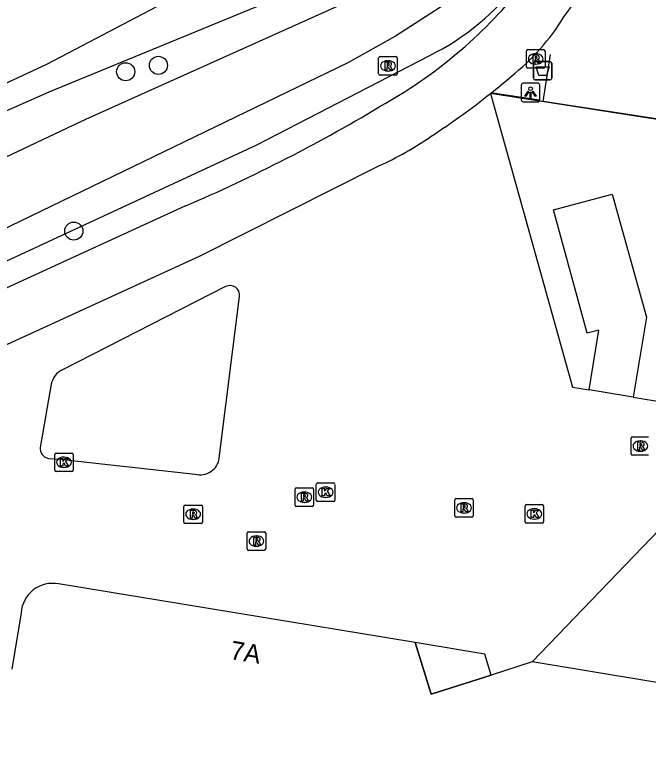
# Model space of a CAD drawing. Extents: x 161094 to 161705, y 379509 to 380907.
# Drawn here: x 161323.43 to 161357.68, y 379952.77 to 379992.35 of the extents above; entities that cross this region are included whole.
import ezdxf

# ---------------------------------------------------------------- set-up
doc = ezdxf.new("R2010")
doc.units = 0
for name, color, linetype in [('IMGEO_Afvalbak', 7, 'Continuous'), ('IMGEO_Boom', 7, 'Continuous'), ('IMGEO_Gemengd_bos', 7, 'Continuous'), ('IMGEO_Groenvoorziening', 7, 'Continuous'), ('IMGEO_Hek', 7, 'Continuous'), ('IMGEO_Kolk', 7, 'Continuous'), ('IMGEO_Lichtpunt', 7, 'Continuous'), ('IMGEO_Pand', 7, 'Continuous'), ('IMGEO_Pand_nummerreeks', 7, 'Continuous'), ('IMGEO_Pand_overbouw', 7, 'Continuous'), ('IMGEO_Rijbaan_lokaal_gesloten', 7, 'Continuous'), ('IMGEO_Rioolput', 7, 'Continuous'), ('IMGEO_Voetpad_open', 7, 'Continuous'), ('IMGEO_Waterloop', 7, 'Continuous')]:
    doc.layers.add(name, color=color, linetype=linetype)

msp = doc.modelspace()

# ---------------------------------------------------------------- linework, layer by layer
at = {"layer": 'IMGEO_Afvalbak'}
for p, q in [((161351.474, 379988.924), (161351.474, 379989.724)), ((161351.474, 379989.724), (161351.474, 379988.924)), ((161351.574, 379989.824), (161352.364, 379989.824)), ((161352.364, 379989.824), (161351.574, 379989.824)), ((161352.464, 379989.724), (161352.464, 379988.924)), ((161352.464, 379988.924), (161352.464, 379989.724)), ((161352.364, 379988.824), (161351.574, 379988.824)), ((161351.574, 379988.824), (161352.364, 379988.824))]:
    msp.add_line(p, q, dxfattribs=at)
msp.add_lwpolyline([(161351.617, 379989.538), (161352.321, 379989.538), (161352.172, 379989.068), (161351.766, 379989.068), (161351.617, 379989.538)], dxfattribs=at)
for centre, start, end in [((161351.574, 379989.724), 90, 180), ((161351.574, 379989.724), 90, 180), ((161352.364, 379989.724), 0, 90), ((161352.364, 379989.724), 360, 90), ((161351.574, 379988.924), 180, 270), ((161351.574, 379988.924), 180, 270), ((161352.364, 379988.924), 270, 0), ((161352.364, 379988.924), 270, 0)]:
    msp.add_arc(centre, 0.1, start, end, dxfattribs=at)
at = {"layer": 'IMGEO_Boom'}
for centre in [(161331.207, 379989.613), (161329.435, 379989.266), (161326.632, 379980.661)]:
    msp.add_circle(centre, 0.489, dxfattribs=at)
at = {"layer": 'IMGEO_Gemengd_bos'}
for points in [[(161333.512, 380038.343), (161333.176, 380032.678), (161343.848, 380009.856), (161345.909, 380004.475), (161345.846, 380002.276), (161345.022, 380001.282), (161342.303, 379999.185), (161336.014, 379995.373), (161325.162, 379989.659), (161249.827, 379954.657)], [(161336.371, 380036.456), (161336.02, 380036.34), (161334.235, 380035.507), (161334.347, 380033.968), (161334.211, 380033.487), (161335.124, 380031.714), (161344.815, 380009.148), (161345.747, 380007.474), (161346.951, 380004.344), (161347.178, 380000.806), (161346.961, 380000), (161346.828, 379999.503), (161346.335, 379998.76), (161344.226, 379996.702), (161341.864, 379995.267), (161336.806, 379992.91), (161325.289, 379988.164), (161318.516, 379985.174), (161250.264, 379953.685)]]:
    msp.add_lwpolyline(points, dxfattribs=at)
at = {"layer": 'IMGEO_Groenvoorziening'}
msp.add_lwpolyline([(161253.412, 379946.694), (161303.367, 379969.522), (161310.516, 379973.076), (161316.928, 379975.983), (161319.974, 379977.646), (161336.524, 379985.328), (161345.842, 379990.137)], dxfattribs=at)
msp.add_arc((161340.204, 380001.802), 12.956, 295.7967, 352.005, dxfattribs=at)
at = {"layer": 'IMGEO_Hek'}
for points in [[(161360.805, 379986.31), (161351.994, 379987.669), (161352.393, 379990.207)], [(161351.787, 379987.734), (161349.286, 379988.105)]]:
    msp.add_lwpolyline(points, dxfattribs=at)
at = {"layer": 'IMGEO_Kolk'}
for p, q in [((161325.598, 379967.742), (161325.598, 379968.594)), ((161325.673, 379968.668), (161326.525, 379968.668)), ((161326.086, 379968.448), (161326.111, 379968.448)), ((161326.599, 379968.594), (161326.599, 379967.742)), ((161326.525, 379967.668), (161325.673, 379967.668)), ((161326.109, 379967.888), (161326.084, 379967.888)), ((161339.739, 379966.127), (161339.739, 379966.979)), ((161339.814, 379967.053), (161340.666, 379967.053)), ((161340.227, 379966.833), (161340.252, 379966.833)), ((161340.74, 379966.979), (161340.74, 379966.127)), ((161340.666, 379966.053), (161339.814, 379966.053)), ((161340.25, 379966.273), (161340.225, 379966.273)), ((161351.024, 379964.956), (161351.024, 379965.808)), ((161351.099, 379965.882), (161351.951, 379965.882)), ((161351.512, 379965.662), (161351.537, 379965.662)), ((161352.025, 379965.808), (161352.025, 379964.956)), ((161351.951, 379964.882), (161351.099, 379964.882)), ((161351.535, 379965.102), (161351.51, 379965.102))]:
    msp.add_line(p, q, dxfattribs=at)
for points in [[(161325.598, 379967.742), (161325.598, 379968.594)], [(161325.673, 379968.668), (161326.525, 379968.668)], [(161325.919, 379968.368), (161326.042, 379968.368), (161326.042, 379968.217), (161326.172, 379968.368), (161326.336, 379968.368), (161326.19, 379968.217), (161326.343, 379967.968), (161326.191, 379967.968), (161326.106, 379968.132), (161326.042, 379968.065), (161326.042, 379967.968), (161325.919, 379967.968), (161325.919, 379968.368)], [(161326.599, 379968.594), (161326.599, 379967.742)], [(161326.525, 379967.668), (161325.673, 379967.668)], [(161339.739, 379966.127), (161339.739, 379966.979)], [(161339.814, 379967.053), (161340.666, 379967.053)], [(161340.06, 379966.753), (161340.183, 379966.753), (161340.183, 379966.602), (161340.313, 379966.753), (161340.477, 379966.753), (161340.331, 379966.602), (161340.484, 379966.353), (161340.332, 379966.353), (161340.247, 379966.517), (161340.183, 379966.45), (161340.183, 379966.353), (161340.06, 379966.353), (161340.06, 379966.753)], [(161340.74, 379966.979), (161340.74, 379966.127)], [(161340.666, 379966.053), (161339.814, 379966.053)], [(161351.024, 379964.956), (161351.024, 379965.808)], [(161351.099, 379965.882), (161351.951, 379965.882)], [(161351.345, 379965.582), (161351.468, 379965.582), (161351.468, 379965.431), (161351.598, 379965.582), (161351.762, 379965.582), (161351.616, 379965.431), (161351.769, 379965.182), (161351.617, 379965.182), (161351.532, 379965.346), (161351.468, 379965.279), (161351.468, 379965.182), (161351.345, 379965.182), (161351.345, 379965.582)], [(161352.025, 379965.808), (161352.025, 379964.956)], [(161351.951, 379964.882), (161351.099, 379964.882)]]:
    msp.add_lwpolyline(points, dxfattribs=at)
for centre, start, end in [((161325.675, 379968.592), 91.552, 178.448), ((161325.675, 379968.592), 91.552, 178.448), ((161326.523, 379968.592), 1.552, 88.448), ((161326.523, 379968.592), 1.552, 88.448), ((161325.675, 379967.744), 181.552, 268.448), ((161325.675, 379967.744), 181.552, 268.448), ((161326.523, 379967.744), 271.552, 358.448), ((161326.523, 379967.744), 271.552, 358.448), ((161339.816, 379966.977), 91.552, 178.448), ((161339.816, 379966.977), 91.552, 178.448), ((161340.664, 379966.977), 1.552, 88.448), ((161340.664, 379966.977), 1.552, 88.448), ((161339.816, 379966.129), 181.552, 268.448), ((161339.816, 379966.129), 181.552, 268.448), ((161340.664, 379966.129), 271.552, 358.448), ((161340.664, 379966.129), 271.552, 358.448), ((161351.101, 379965.806), 91.552, 178.448), ((161351.101, 379965.806), 91.552, 178.448), ((161351.949, 379965.806), 1.552, 88.448), ((161351.949, 379965.806), 1.552, 88.448), ((161351.101, 379964.958), 181.552, 268.448), ((161351.101, 379964.958), 181.552, 268.448), ((161351.949, 379964.958), 271.552, 358.448), ((161351.949, 379964.958), 271.552, 358.448)]:
    msp.add_arc(centre, 0.0765, start, end, dxfattribs=at)
for centre, major_axis, ratio, start_param, end_param in [((161326.085, 379968.168), (-0.387, 0.002), 0.722429, 4.712389, 7.853982), ((161326.11, 379968.168), (-0.39, 0.002), 0.717154, 1.570796, 4.712389), ((161340.226, 379966.553), (-0.387, 0.002), 0.722429, 4.712389, 7.853982), ((161340.251, 379966.553), (-0.39, 0.002), 0.717154, 1.570796, 4.712389), ((161351.511, 379965.382), (-0.387, 0.002), 0.722429, 4.712389, 7.853982), ((161351.536, 379965.382), (-0.39, 0.002), 0.717154, 1.570796, 4.712389)]:
    msp.add_ellipse(centre, major_axis=major_axis, ratio=ratio, start_param=start_param, end_param=end_param, dxfattribs=at)
at = {"layer": 'IMGEO_Lichtpunt'}
for p, q in [((161350.818, 379988.551), (161350.818, 379987.744)), ((161350.818, 379988.551), (161350.818, 379987.744)), ((161351.72, 379988.646), (161350.912, 379988.646)), ((161351.72, 379988.646), (161350.912, 379988.646)), ((161351.814, 379987.744), (161351.814, 379988.551)), ((161351.814, 379987.744), (161351.814, 379988.551)), ((161350.912, 379987.65), (161351.72, 379987.65)), ((161350.912, 379987.65), (161351.72, 379987.65))]:
    msp.add_line(p, q, dxfattribs=at)
for points in [[(161351.192, 379988.215), (161351.231, 379988.187), (161351.043, 379987.925), (161351.005, 379987.952), (161351.192, 379988.215)], [(161351.294, 379988.167), (161351.341, 379988.167), (161351.341, 379987.845), (161351.294, 379987.845), (161351.294, 379988.167)], [(161351.404, 379988.187), (161351.442, 379988.214), (161351.629, 379987.952), (161351.59, 379987.924), (161351.404, 379988.187)]]:
    msp.add_lwpolyline(points, dxfattribs=at)
msp.add_circle((161351.317, 379988.349), 0.0994, dxfattribs=at)
for centre, start, end in [((161350.912, 379988.551), 90, 180), ((161350.912, 379988.551), 90, 180), ((161351.72, 379988.551), 0, 90), ((161351.72, 379988.551), 0, 90), ((161350.912, 379987.744), 180, 270), ((161350.912, 379987.744), 180, 270), ((161351.72, 379987.744), 270, 0), ((161351.72, 379987.744), 270, 360)]:
    msp.add_arc(centre, 0.0946, start, end, dxfattribs=at)
at = {"layer": 'IMGEO_Pand'}
for points in [[(161351.399, 379957.383), (161349.186, 379956.677), (161345.942, 379955.648), (161345.078, 379958.432), (161325.807, 379961.6)], [(161323.784, 379960.039), (161323.28, 379956.993)], [(161368.38, 379956.294), (161364.656, 379955.185), (161351.399, 379957.383)]]:
    msp.add_lwpolyline(points, dxfattribs=at)
msp.add_arc((161325.482, 379959.93), 1.701, 78.9834, 176.326, dxfattribs=at)
at = {"layer": 'IMGEO_Pand_overbouw'}
msp.add_lwpolyline([(161345.078, 379958.432), (161345.942, 379955.648), (161349.186, 379956.677), (161348.84, 379957.806)], close=True, dxfattribs=at)
at = {"layer": 'IMGEO_Rijbaan_lokaal_gesloten'}
for points in [[(161311.588, 379969.309), (161333.424, 379979.297), (161343.123, 379984.181)], [(161332.629, 379982.003), (161281.664, 379958.627), (161253.756, 379945.988)]]:
    msp.add_lwpolyline(points, dxfattribs=at)
for centre, radius, start, end in [((161336.337, 380004.686), 20.899, 323.4272, 347.044), ((161330.698, 380010.021), 25.836, 299.6214, 321.7628), ((161342.689, 379998.614), 12.229, 308.3284, 328.5464), ((161325.995, 380017.238), 37.224, 308.4691, 310.7083), ((161323.98, 380019.636), 40.355, 302.9832, 308.5914), ((161297.957, 380062.954), 88.064, 293.18607, 301.1178), ((161335.403, 380001.075), 18.574, 294.5604, 304.5969)]:
    msp.add_arc(centre, radius, start, end, dxfattribs=at)
at = {"layer": 'IMGEO_Rioolput'}
for p, q in [((161343.183, 379990.087), (161344.035, 379990.087)), ((161351.098, 379989.536), (161351.098, 379990.388)), ((161351.173, 379990.462), (161352.025, 379990.462)), ((161351.586, 379990.242), (161351.611, 379990.242)), ((161352.099, 379990.388), (161352.099, 379989.536)), ((161343.108, 379989.161), (161343.108, 379990.013)), ((161343.596, 379989.867), (161343.621, 379989.867)), ((161344.109, 379990.013), (161344.109, 379989.161)), ((161351.609, 379989.682), (161351.584, 379989.682)), ((161343.619, 379989.307), (161343.594, 379989.307)), ((161352.025, 379989.462), (161351.173, 379989.462)), ((161344.035, 379989.087), (161343.183, 379989.087)), ((161356.832, 379969.549), (161357.684, 379969.549)), ((161356.757, 379968.623), (161356.757, 379969.475)), ((161357.245, 379969.329), (161357.27, 379969.329)), ((161357.268, 379968.769), (161357.243, 379968.769)), ((161357.684, 379968.549), (161356.832, 379968.549)), ((161338.663, 379966.785), (161339.515, 379966.785)), ((161338.588, 379965.859), (161338.588, 379966.711)), ((161339.076, 379966.565), (161339.101, 379966.565)), ((161339.589, 379966.711), (161339.589, 379965.859)), ((161339.099, 379966.005), (161339.074, 379966.005)), ((161347.219, 379965.282), (161347.219, 379966.134)), ((161347.294, 379966.208), (161348.146, 379966.208)), ((161347.707, 379965.988), (161347.732, 379965.988)), ((161348.22, 379966.134), (161348.22, 379965.282)), ((161332.582, 379964.935), (161332.582, 379965.787)), ((161332.657, 379965.861), (161333.509, 379965.861)), ((161333.07, 379965.641), (161333.095, 379965.641)), ((161333.583, 379965.787), (161333.583, 379964.935)), ((161339.515, 379965.785), (161338.663, 379965.785)), ((161348.146, 379965.208), (161347.294, 379965.208)), ((161347.73, 379965.428), (161347.705, 379965.428)), ((161333.509, 379964.861), (161332.657, 379964.861)), ((161333.093, 379965.081), (161333.068, 379965.081)), ((161336.078, 379964.412), (161336.93, 379964.412)), ((161336.003, 379963.486), (161336.003, 379964.338)), ((161336.491, 379964.192), (161336.516, 379964.192)), ((161337.004, 379964.338), (161337.004, 379963.486)), ((161336.514, 379963.632), (161336.489, 379963.632)), ((161336.93, 379963.412), (161336.078, 379963.412))]:
    msp.add_line(p, q, dxfattribs=at)
for points in [[(161343.183, 379990.087), (161344.035, 379990.087)], [(161351.098, 379989.536), (161351.098, 379990.388)], [(161351.173, 379990.462), (161352.025, 379990.462)], [(161351.687, 379990.16), (161351.435, 379990.162), (161351.435, 379989.762)], [(161351.613, 379990.081), (161351.559, 379990.081), (161351.559, 379990)], [(161352.099, 379990.388), (161352.099, 379989.536)], [(161343.108, 379989.161), (161343.108, 379990.013)], [(161343.697, 379989.785), (161343.445, 379989.787), (161343.445, 379989.387)], [(161343.623, 379989.706), (161343.569, 379989.706), (161343.569, 379989.625)], [(161344.109, 379990.013), (161344.109, 379989.161)], [(161351.435, 379989.762), (161351.559, 379989.762), (161351.559, 379989.924), (161351.57, 379989.924)], [(161351.559, 379990), (161351.611, 379990)], [(161351.617, 379989.895), (161351.688, 379989.762), (161351.828, 379989.762), (161351.763, 379989.888)], [(161343.445, 379989.387), (161343.569, 379989.387), (161343.569, 379989.549), (161343.58, 379989.549)], [(161343.569, 379989.625), (161343.621, 379989.625)], [(161343.627, 379989.52), (161343.698, 379989.387), (161343.838, 379989.387), (161343.773, 379989.513)], [(161352.025, 379989.462), (161351.173, 379989.462)], [(161344.035, 379989.087), (161343.183, 379989.087)], [(161356.832, 379969.549), (161357.684, 379969.549)], [(161356.757, 379968.623), (161356.757, 379969.475)], [(161357.346, 379969.247), (161357.094, 379969.249), (161357.094, 379968.849)], [(161357.272, 379969.168), (161357.218, 379969.168), (161357.218, 379969.087)], [(161357.094, 379968.849), (161357.218, 379968.849), (161357.218, 379969.011), (161357.229, 379969.011)], [(161357.218, 379969.087), (161357.27, 379969.087)], [(161357.276, 379968.982), (161357.347, 379968.849), (161357.487, 379968.849), (161357.422, 379968.975)], [(161357.684, 379968.549), (161356.832, 379968.549)], [(161338.663, 379966.785), (161339.515, 379966.785)], [(161338.588, 379965.859), (161338.588, 379966.711)], [(161339.177, 379966.483), (161338.925, 379966.485), (161338.925, 379966.085)], [(161339.103, 379966.404), (161339.049, 379966.404), (161339.049, 379966.323)], [(161339.049, 379966.323), (161339.101, 379966.323)], [(161339.589, 379966.711), (161339.589, 379965.859)], [(161338.925, 379966.085), (161339.049, 379966.085), (161339.049, 379966.247), (161339.06, 379966.247)], [(161339.107, 379966.218), (161339.178, 379966.085), (161339.318, 379966.085), (161339.253, 379966.211)], [(161347.219, 379965.282), (161347.219, 379966.134)], [(161347.294, 379966.208), (161348.146, 379966.208)], [(161348.22, 379966.134), (161348.22, 379965.282)], [(161332.582, 379964.935), (161332.582, 379965.787)], [(161332.657, 379965.861), (161333.509, 379965.861)], [(161333.171, 379965.559), (161332.919, 379965.561), (161332.919, 379965.161)], [(161333.583, 379965.787), (161333.583, 379964.935)], [(161339.515, 379965.785), (161338.663, 379965.785)], [(161347.808, 379965.906), (161347.556, 379965.908), (161347.556, 379965.508)], [(161347.556, 379965.508), (161347.68, 379965.508), (161347.68, 379965.67), (161347.691, 379965.67)], [(161347.734, 379965.827), (161347.68, 379965.827), (161347.68, 379965.746)], [(161347.68, 379965.746), (161347.732, 379965.746)], [(161347.738, 379965.641), (161347.809, 379965.508), (161347.949, 379965.508), (161347.884, 379965.634)], [(161332.919, 379965.161), (161333.043, 379965.161), (161333.043, 379965.323), (161333.054, 379965.323)], [(161333.097, 379965.48), (161333.043, 379965.48), (161333.043, 379965.399)], [(161333.043, 379965.399), (161333.095, 379965.399)], [(161333.101, 379965.294), (161333.172, 379965.161), (161333.312, 379965.161), (161333.247, 379965.287)], [(161348.146, 379965.208), (161347.294, 379965.208)], [(161333.509, 379964.861), (161332.657, 379964.861)], [(161336.078, 379964.412), (161336.93, 379964.412)], [(161336.003, 379963.486), (161336.003, 379964.338)], [(161336.592, 379964.11), (161336.34, 379964.112), (161336.34, 379963.712)], [(161336.518, 379964.031), (161336.464, 379964.031), (161336.464, 379963.95)], [(161336.464, 379963.95), (161336.516, 379963.95)], [(161337.004, 379964.338), (161337.004, 379963.486)], [(161336.34, 379963.712), (161336.464, 379963.712), (161336.464, 379963.874), (161336.475, 379963.874)], [(161336.522, 379963.845), (161336.593, 379963.712), (161336.733, 379963.712), (161336.668, 379963.838)], [(161336.93, 379963.412), (161336.078, 379963.412)]]:
    msp.add_lwpolyline(points, dxfattribs=at)
for centre, radius, start, end in [((161343.185, 379990.011), 0.0765, 91.552, 178.448), ((161343.185, 379990.011), 0.0765, 91.552, 178.448), ((161344.033, 379990.011), 0.0765, 1.552, 88.448), ((161344.033, 379990.011), 0.0765, 1.552, 88.448), ((161351.175, 379990.386), 0.0765, 91.552, 178.448), ((161351.175, 379990.386), 0.0765, 91.552, 178.448), ((161351.619, 379989.985), 0.0964, 77.0061, 93.1865), ((161351.633, 379990.042), 0.0378, 276.6634, 79.6772), ((161351.686, 379990.05), 0.109, 350.3612, 89.416), ((161352.023, 379990.386), 0.0765, 1.552, 88.448), ((161352.023, 379990.386), 0.0765, 1.552, 88.448), ((161343.629, 379989.61), 0.0964, 77.0061, 93.1865), ((161343.643, 379989.667), 0.0378, 276.6634, 79.6772), ((161343.696, 379989.675), 0.109, 350.3612, 89.416), ((161351.569, 379989.871), 0.0533, 26.0293, 88.6989), ((161351.595, 379990.189), 0.19, 274.7715, 282.9687), ((161351.684, 379990.05), 0.112, 277.5842, 350.9817), ((161351.668, 379989.835), 0.108, 29.5134, 73.7905), ((161343.579, 379989.496), 0.0533, 26.0293, 88.6989), ((161343.605, 379989.814), 0.19, 274.7715, 282.9687), ((161343.694, 379989.675), 0.112, 277.5842, 350.9817), ((161343.678, 379989.46), 0.108, 29.5134, 73.7905), ((161351.175, 379989.538), 0.0765, 181.552, 268.448), ((161351.175, 379989.538), 0.0765, 181.552, 268.448), ((161352.023, 379989.538), 0.0765, 271.552, 358.448), ((161352.023, 379989.538), 0.0765, 271.552, 358.448), ((161343.185, 379989.163), 0.0765, 181.552, 268.448), ((161343.185, 379989.163), 0.0765, 181.552, 268.448), ((161344.033, 379989.163), 0.0765, 271.552, 358.448), ((161344.033, 379989.163), 0.0765, 271.552, 358.448), ((161356.834, 379969.473), 0.0765, 91.552, 178.448), ((161356.834, 379969.473), 0.0765, 91.552, 178.448), ((161357.278, 379969.072), 0.0964, 77.0061, 93.1865), ((161357.292, 379969.129), 0.0378, 276.6634, 79.6772), ((161357.345, 379969.137), 0.109, 350.3612, 89.416), ((161357.343, 379969.137), 0.112, 277.5842, 350.9817), ((161357.228, 379968.958), 0.0533, 26.0293, 88.6989), ((161357.254, 379969.276), 0.19, 274.7715, 282.9687), ((161357.327, 379968.922), 0.108, 29.5134, 73.7905), ((161356.834, 379968.625), 0.0765, 181.552, 268.448), ((161356.834, 379968.625), 0.0765, 181.552, 268.448), ((161338.665, 379966.709), 0.0765, 91.552, 178.448), ((161338.665, 379966.709), 0.0765, 91.552, 178.448), ((161339.513, 379966.709), 0.0765, 1.552, 88.448), ((161339.513, 379966.709), 0.0765, 1.552, 88.448), ((161339.085, 379966.512), 0.19, 274.7715, 282.9687), ((161339.109, 379966.308), 0.0964, 77.0061, 93.1865), ((161339.123, 379966.365), 0.0378, 276.6634, 79.6772), ((161339.176, 379966.373), 0.109, 350.3612, 89.416), ((161339.174, 379966.373), 0.112, 277.5842, 350.9817), ((161339.059, 379966.194), 0.0533, 26.0293, 88.6989), ((161339.158, 379966.158), 0.108, 29.5134, 73.7905), ((161347.296, 379966.132), 0.0765, 91.552, 178.448), ((161347.296, 379966.132), 0.0765, 91.552, 178.448), ((161348.144, 379966.132), 0.0765, 1.552, 88.448), ((161348.144, 379966.132), 0.0765, 1.552, 88.448), ((161332.659, 379965.785), 0.0765, 91.552, 178.448), ((161332.659, 379965.785), 0.0765, 91.552, 178.448), ((161333.17, 379965.449), 0.109, 350.3612, 89.416), ((161333.507, 379965.785), 0.0765, 1.552, 88.448), ((161333.507, 379965.785), 0.0765, 1.552, 88.448), ((161338.665, 379965.861), 0.0765, 181.552, 268.448), ((161338.665, 379965.861), 0.0765, 181.552, 268.448), ((161339.513, 379965.861), 0.0765, 271.552, 358.448), ((161339.513, 379965.861), 0.0765, 271.552, 358.448), ((161347.69, 379965.617), 0.0533, 26.0293, 88.6989), ((161347.716, 379965.935), 0.19, 274.7715, 282.9687), ((161347.74, 379965.731), 0.0964, 77.0061, 93.1865), ((161347.754, 379965.788), 0.0378, 276.6634, 79.6772), ((161347.807, 379965.796), 0.109, 350.3612, 89.416), ((161347.805, 379965.796), 0.112, 277.5842, 350.9817), ((161347.789, 379965.581), 0.108, 29.5134, 73.7905), ((161333.053, 379965.27), 0.0533, 26.0293, 88.6989), ((161333.079, 379965.588), 0.19, 274.7715, 282.9687), ((161333.103, 379965.384), 0.0964, 77.0061, 93.1865), ((161333.117, 379965.441), 0.0378, 276.6634, 79.6772), ((161333.168, 379965.449), 0.112, 277.5842, 350.9817), ((161333.152, 379965.234), 0.108, 29.5134, 73.7905), ((161347.296, 379965.284), 0.0765, 181.552, 268.448), ((161347.296, 379965.284), 0.0765, 181.552, 268.448), ((161348.144, 379965.284), 0.0765, 271.552, 358.448), ((161348.144, 379965.284), 0.0765, 271.552, 358.448), ((161332.659, 379964.937), 0.0765, 181.552, 268.448), ((161332.659, 379964.937), 0.0765, 181.552, 268.448), ((161333.507, 379964.937), 0.0765, 271.552, 358.448), ((161333.507, 379964.937), 0.0765, 271.552, 358.448), ((161336.08, 379964.336), 0.0765, 91.552, 178.448), ((161336.08, 379964.336), 0.0765, 91.552, 178.448), ((161336.928, 379964.336), 0.0765, 1.552, 88.448), ((161336.928, 379964.336), 0.0765, 1.552, 88.448), ((161336.5, 379964.139), 0.19, 274.7715, 282.9687), ((161336.524, 379963.935), 0.0964, 77.0061, 93.1865), ((161336.538, 379963.992), 0.0378, 276.6634, 79.6772), ((161336.591, 379964), 0.109, 350.3612, 89.416), ((161336.589, 379964), 0.112, 277.5842, 350.9817), ((161336.474, 379963.821), 0.0533, 26.0293, 88.6989), ((161336.573, 379963.785), 0.108, 29.5134, 73.7905), ((161336.08, 379963.488), 0.0765, 181.552, 268.448), ((161336.08, 379963.488), 0.0765, 181.552, 268.448), ((161336.928, 379963.488), 0.0765, 271.552, 358.448), ((161336.928, 379963.488), 0.0765, 271.552, 358.448)]:
    msp.add_arc(centre, radius, start, end, dxfattribs=at)
for centre, major_axis, ratio, start_param, end_param in [((161351.585, 379989.962), (-0.387, 0.002), 0.722429, 4.712389, 7.853982), ((161351.61, 379989.962), (-0.39, 0.002), 0.717154, 1.570796, 4.712389), ((161343.595, 379989.587), (-0.387, 0.002), 0.722429, 4.712389, 7.853982), ((161343.62, 379989.587), (-0.39, 0.002), 0.717154, 1.570796, 4.712389), ((161357.244, 379969.049), (-0.387, 0.002), 0.722429, 4.712389, 7.853982), ((161357.269, 379969.049), (-0.39, 0.002), 0.717154, 1.570796, 4.712389), ((161339.075, 379966.285), (-0.387, 0.002), 0.722429, 4.712389, 7.853982), ((161339.1, 379966.285), (-0.39, 0.002), 0.717154, 1.570796, 4.712389), ((161347.706, 379965.708), (-0.387, 0.002), 0.722429, 4.712389, 7.853982), ((161347.731, 379965.708), (-0.39, 0.002), 0.717154, 1.570796, 4.712389), ((161333.069, 379965.361), (-0.387, 0.002), 0.722429, 4.712389, 7.853982), ((161333.094, 379965.361), (-0.39, 0.002), 0.717154, 1.570796, 4.712389), ((161336.49, 379963.912), (-0.387, 0.002), 0.722429, 4.712389, 7.853982), ((161336.515, 379963.912), (-0.39, 0.002), 0.717154, 1.570796, 4.712389)]:
    msp.add_ellipse(centre, major_axis=major_axis, ratio=ratio, start_param=start_param, end_param=end_param, dxfattribs=at)
at = {"layer": 'IMGEO_Voetpad_open'}
for points in [[(161349.152, 379988.094), (161353.577, 379972.23), (161354.48, 379972.081)], [(161360.935, 379986.257), (161349.152, 379988.094)], [(161354.48, 379972.081), (161355.014, 379975.299), (161354.383, 379975.137), (161352.556, 379981.803), (161355.728, 379982.655), (161357.587, 379976.01), (161356.858, 379971.692)], [(161334.839, 379977.666), (161326.021, 379973.173)], [(161334.496, 379968.4), (161335.592, 379977.135)], [(161325.416, 379972.384), (161324.819, 379968.976)], [(161356.858, 379971.692), (161354.48, 379972.081)], [(161356.858, 379971.692), (161358.609, 379971.404)], [(161325.269, 379968.378), (161325.873, 379968.331)], [(161325.873, 379968.331), (161333.185, 379967.537)], [(161362.006, 379964.159), (161358.278, 379964.544), (161351.399, 379957.383)]]:
    msp.add_lwpolyline(points, dxfattribs=at)
for centre, radius, start, end in [((161335.073, 379977.198), 0.523, 353.0575, 116.5611), ((161326.467, 379972.205), 1.066, 114.7138, 170.3247), ((161325.361, 379968.916), 0.546, 173.6526, 260.2709), ((161333.465, 379968.539), 1.041, 254.3979, 352.314)]:
    msp.add_arc(centre, radius, start, end, dxfattribs=at)
at = {"layer": 'IMGEO_Waterloop'}
for points in [[(161251.099, 379951.83), (161306.446, 379977.244), (161317.242, 379981.964), (161327.279, 379986.7), (161344.808, 379994.589)], [(161348.33, 379993.974), (161344.015, 379991.183), (161341.448, 379989.744), (161313.23, 379976.116), (161295.894, 379968.025), (161252.681, 379948.316)]]:
    msp.add_lwpolyline(points, dxfattribs=at)

# ---------------------------------------------------------------- texts
at = {"layer": 'IMGEO_Pand_nummerreeks'}
msp.add_text('7A', height=1, rotation=350.6648, dxfattribs=at).set_placement((161335.035, 379957.549))

doc.saveas('drawing.dxf')
